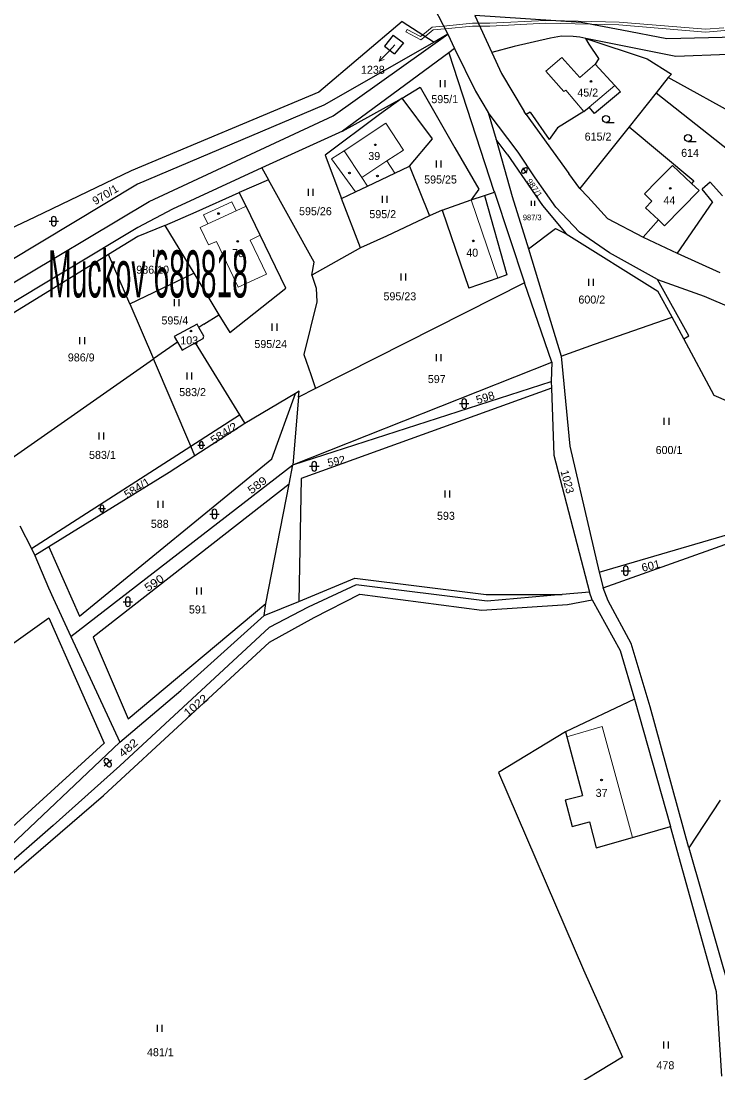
# Model space of a CAD drawing. Extents: x -744132 to -742433, y -984679 to -982287.
# Drawn here: x -743105 to -742956.9, y -983532.9 to -983309.4 of the extents above; entities that cross this region are included whole.
import ezdxf
from ezdxf.enums import TextEntityAlignment as Align

# ---------------------------------------------------------------- set-up
doc = ezdxf.new("R2010")
doc.units = 0
doc.header["$LTSCALE"] = 0.68
for name, color, linetype, lineweight in [('1', 7, 'Continuous', 25), ('13', 7, 'Continuous', 13), ('3', 7, 'Continuous', 25), ('4', 7, 'Continuous', 13), ('5', 7, 'Continuous', 25), ('7', 7, 'Continuous', 13)]:
    doc.layers.add(name, color=color, linetype=linetype, lineweight=lineweight)
doc.layers.add('2', color=7, linetype='Continuous')

msp = doc.modelspace()

# ---------------------------------------------------------------- linework, layer by layer
at = {"layer": '1'}
for p, q in [((-743035.42, -983270.81), (-743014.36, -983312.19)), ((-743024.03, -983309.45), (-743041.74, -983324.46)), ((-743024.03, -983309.45), (-743017.27, -983313.86)), ((-743008.63, -983308.2), (-743004.99, -983316.04)), ((-742986.03, -983309.69), (-743008.63, -983308.2)), ((-742977.36, -983311.34), (-742986.03, -983309.69)), ((-743038.73, -983329.48), (-743014.36, -983312.19)), ((-743014.36, -983312.19), (-743017.27, -983313.86)), ((-743014.36, -983312.19), (-743012.89, -983315.2)), ((-742967.82, -983313.13), (-742977.36, -983311.34)), ((-743017.27, -983313.86), (-743040.69, -983327.27)), ((-743025.95, -983312.38), (-743027.82, -983314.74)), ((-743025.95, -983312.38), (-743023.77, -983313.99)), ((-743023.77, -983313.99), (-743025.64, -983316.35)), ((-742992.51, -983313.01), (-743000.27, -983314.78)), ((-742990.17, -983312.59), (-742992.51, -983313.01)), ((-742987.7, -983312.64), (-742990.17, -983312.59)), ((-742986.3, -983312.77), (-742987.7, -983312.64)), ((-742985.04, -983313.07), (-742986.3, -983312.77)), ((-742985.04, -983313.07), (-742971.98, -983317.4)), ((-742965.92, -983316.88), (-742985.04, -983313.07)), ((-742984.3, -983314.25), (-742985.04, -983313.07)), ((-742982.27, -983317.36), (-742984.3, -983314.25)), ((-742953.06, -983312.8), (-742967.82, -983313.13)), ((-743014.11, -983316.1), (-743036.74, -983332.76)), ((-743027.82, -983314.74), (-743025.64, -983316.35)), ((-743012.89, -983315.2), (-743014.11, -983316.1)), ((-743014.11, -983316.1), (-743004.54, -983345.5)), ((-743012.89, -983315.2), (-743008.45, -983324.28)), ((-743000.27, -983314.78), (-743004.99, -983316.04)), ((-743004.99, -983316.04), (-743002.95, -983320.48)), ((-742954.79, -983316.51), (-742965.92, -983316.88)), ((-742982.27, -983317.36), (-742983.03, -983318.5)), ((-742983.03, -983318.5), (-742978.89, -983323.05)), ((-742971.98, -983317.4), (-742966.84, -983320.68)), ((-743002.95, -983320.48), (-742998.09, -983328.58)), ((-742966.84, -983320.68), (-742967.49, -983321.4)), ((-742978.89, -983323.05), (-742977.66, -983324.4)), ((-742967.49, -983321.4), (-742970.08, -983324.65)), ((-742948.13, -983332.12), (-742967.49, -983321.4)), ((-743041.74, -983324.46), (-743081.64, -983341.21)), ((-743008.45, -983324.28), (-743005.76, -983328.83)), ((-742977.66, -983324.4), (-742983.17, -983329.03)), ((-742970.08, -983324.65), (-742975.8, -983331.88)), ((-742970.08, -983324.65), (-742949.55, -983340.86)), ((-743040.69, -983327.27), (-743080.3, -983344.02)), ((-743036.74, -983332.76), (-743024.02, -983325.74)), ((-743024.02, -983325.74), (-743028.89, -983329.26)), ((-743017.59, -983334.39), (-743024.02, -983325.74)), ((-742985.42, -983328.59), (-742984.32, -983327.66)), ((-742983.17, -983329.03), (-742984.32, -983327.66)), ((-743077.8, -983347.74), (-743038.73, -983329.48)), ((-743028.89, -983329.26), (-743040.43, -983337.85)), ((-743005.76, -983328.83), (-743004.07, -983334.51)), ((-742999.37, -983337.21), (-743005.76, -983328.83)), ((-742997.67, -983329.25), (-742998.09, -983328.58)), ((-742996.84, -983328.74), (-742997.67, -983329.25)), ((-742997.67, -983329.25), (-742988.64, -983341.75)), ((-742996.84, -983328.74), (-742992.81, -983334.57)), ((-742985.42, -983328.59), (-742991.05, -983332.04)), ((-742991.05, -983332.04), (-742992.81, -983334.57)), ((-742975.8, -983331.88), (-742986.28, -983344.96)), ((-742975.8, -983331.88), (-742962.07, -983343.35)), ((-743036.74, -983332.76), (-743053.86, -983340.56)), ((-743022.48, -983340.2), (-743017.59, -983334.39)), ((-743004.07, -983334.51), (-743000.68, -983346.67)), ((-743001.7, -983337.68), (-743004.07, -983334.51)), ((-743040.43, -983337.85), (-743036.96, -983347.06)), ((-743001.7, -983337.68), (-742994.19, -983348.56)), ((-742995.8, -983342.65), (-742999.37, -983337.21)), ((-743081.64, -983341.21), (-743102.11, -983351.03)), ((-743053.86, -983340.56), (-743072.8, -983349.33)), ((-743053.86, -983340.56), (-743052.44, -983343.13)), ((-743025.58, -983341.67), (-743022.48, -983340.2)), ((-743022.48, -983340.2), (-743018.21, -983350.78)), ((-743052.44, -983343.13), (-743058.7, -983345.79)), ((-743031.41, -983344.43), (-743025.58, -983341.67)), ((-742991.41, -983348.94), (-742995.8, -983342.65)), ((-742986.28, -983344.96), (-742988.64, -983341.75)), ((-742962.07, -983343.35), (-742962.56, -983343.88)), ((-743080.3, -983344.02), (-743107.71, -983360.5)), ((-743036.96, -983347.06), (-743033.97, -983345.64)), ((-743033.97, -983345.64), (-743031.41, -983344.43)), ((-743006.52, -983346.43), (-743004.45, -983345.76)), ((-743004.54, -983345.5), (-743004.45, -983345.76)), ((-743004.45, -983345.76), (-742998.04, -983364.96)), ((-742986.28, -983344.96), (-742984.62, -983346.71)), ((-742960.95, -983345.39), (-742968.27, -983352.89)), ((-742960.95, -983345.39), (-742962.56, -983343.88)), ((-742958.59, -983343.6), (-742960.29, -983345.12)), ((-742958.08, -983347.8), (-742960.29, -983345.12)), ((-742958.59, -983343.6), (-742956, -983346.48)), ((-743123.79, -983375.17), (-743077.8, -983347.74)), ((-743067.84, -983349.87), (-743058.7, -983345.79)), ((-743057.18, -983348.71), (-743058.7, -983345.79)), ((-743032.88, -983357.57), (-743036.96, -983347.06)), ((-743015.56, -983349.54), (-743009.41, -983347.37)), ((-743009.41, -983347.37), (-743006.52, -983346.43)), ((-743006.52, -983346.43), (-743001.77, -983363.3)), ((-743000.68, -983346.67), (-742997.17, -983357.74)), ((-742984.62, -983346.71), (-742980.38, -983351.31)), ((-742958.08, -983347.8), (-742965.59, -983358.65)), ((-743072.8, -983349.33), (-743080.22, -983353.24)), ((-743074.49, -983352.84), (-743067.84, -983349.87)), ((-743054.21, -983354.89), (-743057.18, -983348.71)), ((-743015.56, -983349.54), (-743018.21, -983350.78)), ((-743015.56, -983349.54), (-743009.85, -983366.15)), ((-742994.19, -983348.56), (-742989.17, -983354.57)), ((-742986.38, -983354.23), (-742991.41, -983348.94)), ((-743102.11, -983351.03), (-743115.65, -983357.39)), ((-743018.21, -983350.78), (-743027.39, -983355.06)), ((-742980.38, -983351.31), (-742972.82, -983355.31)), ((-742969.6, -983351.58), (-742972.82, -983355.31)), ((-742969.6, -983351.58), (-742968.27, -983352.89)), ((-743080.22, -983353.24), (-743116.02, -983374.77)), ((-743074.49, -983352.84), (-743080.18, -983355.17)), ((-743074.49, -983352.84), (-743068.27, -983362.96)), ((-742997.17, -983357.74), (-742991.46, -983353.48)), ((-742991.46, -983353.48), (-742989.17, -983354.57)), ((-742989.17, -983354.57), (-742969.73, -983366.75)), ((-742980.01, -983358.58), (-742986.38, -983354.23)), ((-743080.18, -983355.17), (-743086.44, -983359)), ((-743048.79, -983366.15), (-743054.21, -983354.89)), ((-743027.39, -983355.06), (-743032.88, -983357.57)), ((-742972.82, -983355.31), (-742965.59, -983358.65)), ((-743086.44, -983359), (-743114.52, -983376.21)), ((-743081.89, -983369.48), (-743086.44, -983359)), ((-743032.88, -983357.57), (-743043.21, -983363.39)), ((-742997.17, -983357.74), (-742995.05, -983364.75)), ((-742969.76, -983364.29), (-742980.01, -983358.58)), ((-742965.59, -983358.65), (-742956.57, -983362.81)), ((-743081.89, -983369.48), (-743068.27, -983362.96)), ((-743068.27, -983362.96), (-743063, -983371.81)), ((-743043.21, -983363.39), (-743042.33, -983366.15)), ((-743001.77, -983363.3), (-743003.7, -983363.98)), ((-742998.04, -983364.96), (-743042.45, -983387.46)), ((-743003.7, -983363.98), (-743009.85, -983366.15)), ((-742992.26, -983381.84), (-742998.04, -983364.96)), ((-742995.05, -983364.75), (-742990.26, -983380.54)), ((-742969.76, -983364.29), (-742959.86, -983367.82)), ((-742963.15, -983376.22), (-742969.76, -983364.29)), ((-743060.68, -983375.56), (-743048.79, -983366.15)), ((-743042.33, -983366.15), (-743042.17, -983369.01)), ((-742959.86, -983367.82), (-742954.09, -983370.28)), ((-743081.89, -983369.48), (-743076.85, -983381.14)), ((-743042.17, -983369.01), (-743044.9, -983380.24)), ((-743066.2, -983373.74), (-743063, -983371.81)), ((-743063, -983371.81), (-743060.68, -983375.56)), ((-742983.17, -983378.05), (-742966.71, -983372.27)), ((-743067.59, -983373.78), (-743072.47, -983376.37)), ((-743067.23, -983374.45), (-743067.59, -983373.78)), ((-743066.2, -983373.74), (-743067.23, -983374.45)), ((-743066.2, -983376.35), (-743067.23, -983374.45)), ((-743072.47, -983376.37), (-743071.77, -983377.59)), ((-743068.04, -983377.76), (-743066.29, -983376.81)), ((-743066.29, -983376.81), (-743066.2, -983376.35)), ((-742964.19, -983376.89), (-742963.15, -983376.22)), ((-742957.77, -983388.91), (-742964.19, -983376.89)), ((-743071.77, -983377.59), (-743076.85, -983381.14)), ((-743071.77, -983377.59), (-743070.81, -983379.26)), ((-743070.81, -983379.26), (-743068.04, -983377.76)), ((-742990.26, -983380.54), (-742983.17, -983378.05)), ((-743108.52, -983403.29), (-743076.85, -983381.14)), ((-743068.94, -983399.66), (-743076.85, -983381.14)), ((-743044.9, -983380.24), (-743043.47, -983384.43)), ((-742990.26, -983380.54), (-742988.4, -983399.7)), ((-743047.27, -983403.67), (-742992.26, -983381.84)), ((-742992.26, -983381.84), (-742992.36, -983385.92)), ((-743047.27, -983403.67), (-742992.36, -983385.92)), ((-743043.47, -983384.43), (-743042.45, -983387.46)), ((-742992.36, -983385.92), (-742992.33, -983387.4)), ((-743045.89, -983388.03), (-743046.72, -983388.52)), ((-743042.45, -983387.46), (-743046.08, -983389.3)), ((-743046.08, -983389.3), (-743045.89, -983388.03)), ((-742992.33, -983387.4), (-743045.48, -983406.58)), ((-742992.33, -983387.4), (-742991.79, -983401.6)), ((-743046.72, -983388.52), (-743057.49, -983394.87)), ((-743051.73, -983402.37), (-743046.72, -983388.52)), ((-743046.08, -983389.3), (-743047.27, -983403.67)), ((-742954.64, -983390.28), (-742957.77, -983388.91)), ((-743068.94, -983399.66), (-743058.63, -983393.03)), ((-743057.49, -983394.87), (-743068.06, -983401.72)), ((-743102.82, -983421.45), (-743068.94, -983399.66)), ((-743068.06, -983401.72), (-743068.94, -983399.66)), ((-742991.79, -983401.6), (-742984.24, -983430.7)), ((-742988.4, -983399.7), (-742982.15, -983426.48)), ((-743094.45, -983440.1), (-743047.27, -983403.67)), ((-743092.61, -983435.78), (-743051.73, -983402.37)), ((-743068.06, -983401.72), (-743073.57, -983405.29)), ((-743048.05, -983407.76), (-743047.27, -983403.67)), ((-743073.57, -983405.29), (-743099.13, -983421.05)), ((-743048.05, -983407.76), (-743089.67, -983440.29)), ((-743052.97, -983433.12), (-743048.05, -983407.76)), ((-743105.28, -983416.64), (-743102.82, -983421.45)), ((-742982.15, -983426.48), (-742954.34, -983418.3)), ((-743102.82, -983421.45), (-743102.08, -983422.89)), ((-743099.13, -983421.05), (-743102.08, -983422.89)), ((-743099.13, -983421.05), (-743092.61, -983435.78)), ((-742981.35, -983429.8), (-742953.31, -983419.82)), ((-743102.08, -983422.89), (-743099.18, -983429.82)), ((-742982.15, -983426.48), (-742981.35, -983429.8)), ((-743099.18, -983429.82), (-743098.21, -983432.01)), ((-743033.82, -983429.18), (-743044.04, -983433.86)), ((-743005.99, -983432.63), (-743033.82, -983429.18)), ((-742980.29, -983432.52), (-742981.35, -983429.8)), ((-743098.21, -983432.01), (-743094.45, -983440.1)), ((-743053.39, -983435.69), (-743046, -983432.72)), ((-743042.77, -983436.07), (-743033.06, -983431.15)), ((-743033.06, -983431.15), (-743007.08, -983434.54)), ((-742990.05, -983431.22), (-743005.99, -983432.63)), ((-742984.24, -983430.7), (-742990.05, -983431.22)), ((-742988.94, -983433.31), (-742983.67, -983432.36)), ((-742983.67, -983432.36), (-742984.24, -983430.7)), ((-742983.67, -983432.36), (-742977.71, -983443.12)), ((-742975.41, -983441.62), (-742980.29, -983432.52)), ((-743082.25, -983457.59), (-743052.97, -983433.12)), ((-743053.39, -983435.69), (-743052.97, -983433.12)), ((-743044.04, -983433.86), (-743052.32, -983438.22)), ((-743007.08, -983434.54), (-742988.94, -983433.31)), ((-743123.13, -983453.28), (-743099.09, -983436.19)), ((-743099.09, -983436.19), (-743087.36, -983462.79)), ((-743071.04, -983451.59), (-743053.39, -983435.69)), ((-743052.23, -983441.33), (-743042.77, -983436.07)), ((-743052.32, -983438.22), (-743084.04, -983467.59)), ((-743094.45, -983440.1), (-743084, -983462.6)), ((-743089.67, -983440.29), (-743082.25, -983457.59)), ((-743087.48, -983473.88), (-743052.23, -983441.33)), ((-742971.35, -983455.07), (-742975.41, -983441.62)), ((-742977.71, -983443.12), (-742974.65, -983453.47)), ((-743084, -983462.6), (-743071.04, -983451.59)), ((-742974.65, -983453.47), (-742989.34, -983460.35)), ((-742974.65, -983453.47), (-742967.03, -983480.49)), ((-742963.11, -983485), (-742971.35, -983455.07)), ((-742989.34, -983460.35), (-743003.6, -983468.99)), ((-742989.34, -983460.35), (-742989.05, -983461.43)), ((-742989.05, -983461.43), (-742985.76, -983473.89)), ((-743087.36, -983462.79), (-743127.53, -983499.42)), ((-743084, -983462.6), (-743125.36, -983501.7)), ((-743084.04, -983467.59), (-743098.21, -983480.3)), ((-743003.6, -983468.99), (-742985.48, -983510.94)), ((-743122.91, -983504.38), (-743087.48, -983473.88)), ((-742989.39, -983474.84), (-742985.76, -983473.89)), ((-742989.39, -983474.84), (-742987.9, -983480.48)), ((-742956.48, -983474.86), (-742963.11, -983485)), ((-742987.9, -983480.48), (-742984.27, -983479.51)), ((-742984.27, -983479.51), (-742982.82, -983485)), ((-743098.21, -983480.3), (-743124.44, -983503.22)), ((-742975.13, -983482.8), (-742967.03, -983480.49)), ((-742957.26, -983515.6), (-742967.03, -983480.49)), ((-742982.82, -983485), (-742975.13, -983482.8)), ((-742963.11, -983485), (-742954.27, -983515.9)), ((-742985.48, -983510.94), (-742977.21, -983529.47)), ((-742956.14, -983533.56), (-742957.26, -983515.6)), ((-742977.21, -983529.47), (-742989.65, -983537))]:
    msp.add_line(p, q, dxfattribs=at)
for points in [[(-743024.02, -983325.74), (-743020.24, -983323.42), (-743012.82, -983336.31), (-743007.77, -983345.06), (-743009.41, -983347.37)], [(-743043.21, -983363.39), (-743042.74, -983360.61), (-743052.44, -983343.13)], [(-742964.19, -983376.89), (-742966.71, -983372.27), (-742969.73, -983366.75)], [(-743068.04, -983377.76), (-743058.63, -983393.03), (-743057.49, -983394.87)], [(-743045.48, -983406.58), (-743046, -983432.72), (-743034.13, -983427.73)], [(-743034.13, -983427.73), (-743006.21, -983431.17), (-742990.05, -983431.22)]]:
    msp.add_lwpolyline(points, dxfattribs=at)
at = {"layer": '13'}
for points in [[(-743015.25, -983310.43), (-743014.96, -983311.01), (-743009.11, -983310.43), (-743007.59, -983310.44), (-743007.87, -983309.84), (-743009.13, -983309.83)], [(-743015.25, -983310.43), (-743017.67, -983310.67), (-743019.67, -983312.29), (-743020.14, -983312.67), (-743022.95, -983311.15), (-743023.23, -983311.67), (-743020.08, -983313.39), (-743019.15, -983312.64), (-743017.43, -983311.25), (-743014.96, -983311.01)]]:
    msp.add_lwpolyline(points, close=True, dxfattribs=at)
msp.add_lwpolyline([(-742955.72, -983310.79), (-742959.6, -983311.1), (-742977.96, -983309.6), (-742992.46, -983309.27), (-742993.59, -983309.24), (-743005.41, -983309.85), (-743007.87, -983309.84), (-743007.59, -983310.44), (-743005.39, -983310.45), (-742993.59, -983309.84), (-742984.09, -983310.06), (-742978, -983310.2), (-742959.6, -983311.7), (-742955.5, -983311.37)], dxfattribs=at)
at = {"layer": '3'}
for p, q in [((-743015.871, -983323.43), (-743015.871, -983321.93)), ((-743014.87, -983323.43), (-743014.87, -983321.93)), ((-742980.743, -983330.93), (-742978.993, -983330.93)), ((-742963.313, -983334.97), (-742961.563, -983334.97)), ((-743016.761, -983340.51), (-743016.761, -983339.01)), ((-743015.76, -983340.51), (-743015.76, -983339.01)), ((-742998.003, -983340.618), (-742998.562, -983341.04)), ((-742998.493, -983340.55), (-742997.65, -983341.669)), ((-742998.141, -983341.6), (-742997.581, -983341.178)), ((-743043.921, -983346.53), (-743043.921, -983345.03)), ((-743042.92, -983346.53), (-743042.92, -983345.03)), ((-743028.231, -983347.99), (-743028.231, -983346.49)), ((-743027.23, -983347.99), (-743027.23, -983346.49)), ((-742996.568, -983348.62), (-742996.568, -983347.57)), ((-742995.867, -983348.62), (-742995.867, -983347.57)), ((-743099.071, -983351.901), (-743097.069, -983351.901)), ((-743098.571, -983351.401), (-743098.571, -983352.402)), ((-743097.569, -983352.402), (-743097.569, -983351.401)), ((-743076.791, -983359.48), (-743076.791, -983357.98)), ((-743075.79, -983359.48), (-743075.79, -983357.98)), ((-743024.271, -983364.52), (-743024.271, -983363.02)), ((-743023.27, -983364.52), (-743023.27, -983363.02)), ((-742984.361, -983365.61), (-742984.361, -983364.11)), ((-742983.36, -983365.61), (-742983.36, -983364.11)), ((-743072.391, -983369.97), (-743072.391, -983368.47)), ((-743071.39, -983369.97), (-743071.39, -983368.47)), ((-743051.631, -983375.16), (-743051.631, -983373.66)), ((-743050.63, -983375.16), (-743050.63, -983373.66)), ((-743092.491, -983378.05), (-743092.491, -983376.55)), ((-743091.49, -983378.05), (-743091.49, -983376.55)), ((-743016.771, -983381.66), (-743016.771, -983380.16)), ((-743015.77, -983381.66), (-743015.77, -983380.16)), ((-743069.741, -983385.53), (-743069.741, -983384.03)), ((-743068.74, -983385.53), (-743068.74, -983384.03)), ((-743011.361, -983390.151), (-743011.361, -983391.152)), ((-743010.359, -983391.152), (-743010.359, -983390.151)), ((-743011.861, -983390.651), (-743009.859, -983390.651)), ((-742968.341, -983395.18), (-742968.341, -983393.68)), ((-742967.34, -983395.18), (-742967.34, -983393.68)), ((-743088.421, -983398.3), (-743088.421, -983396.8)), ((-743087.42, -983398.3), (-743087.42, -983396.8)), ((-743067.075, -983399.075), (-743067.075, -983399.826)), ((-743066.325, -983399.826), (-743066.325, -983399.075)), ((-743067.451, -983399.451), (-743065.949, -983399.451)), ((-743043.211, -983403.471), (-743043.211, -983404.472)), ((-743042.209, -983404.472), (-743042.209, -983403.471)), ((-743043.711, -983403.971), (-743041.709, -983403.971)), ((-743014.931, -983410.6), (-743014.931, -983409.1)), ((-743013.93, -983410.6), (-743013.93, -983409.1)), ((-743088.185, -983412.575), (-743088.185, -983413.326)), ((-743087.435, -983413.326), (-743087.435, -983412.575)), ((-743075.851, -983412.77), (-743075.851, -983411.27)), ((-743074.85, -983412.77), (-743074.85, -983411.27)), ((-743088.561, -983412.951), (-743087.059, -983412.951)), ((-743064.921, -983414.101), (-743062.919, -983414.101)), ((-743064.421, -983413.601), (-743064.421, -983414.602)), ((-743063.419, -983414.602), (-743063.419, -983413.601)), ((-742977.541, -983426.151), (-742975.539, -983426.151)), ((-742977.041, -983425.651), (-742977.041, -983426.652)), ((-742976.039, -983426.652), (-742976.039, -983425.651)), ((-743067.651, -983431.19), (-743067.651, -983429.69)), ((-743066.65, -983431.19), (-743066.65, -983429.69)), ((-743083.321, -983432.741), (-743081.319, -983432.741)), ((-743082.821, -983432.241), (-743082.821, -983433.242)), ((-743081.819, -983433.242), (-743081.819, -983432.241)), ((-743087.367, -983467.574), (-743085.811, -983466.314)), ((-743085.885, -983467.018), (-743086.515, -983466.24)), ((-743087.293, -983466.87), (-743086.663, -983467.648)), ((-743076.011, -983524.14), (-743076.011, -983522.64)), ((-743075.01, -983524.14), (-743075.01, -983522.64)), ((-742968.421, -983527.67), (-742968.421, -983526.17)), ((-742967.42, -983527.67), (-742967.42, -983526.17))]:
    msp.add_line(p, q, dxfattribs=at)
for centre in [(-742980.7429, -983330.1798), (-742963.3129, -983334.2198)]:
    msp.add_circle(centre, 0.75, dxfattribs=at)
for centre, radius, start, end in [((-742998.351, -983341.3197), 0.35, 127, 306.98789), ((-742997.7919, -983340.8985), 0.35, 307, 127), ((-743098.07, -983351.4009), 0.5, 0, 180), ((-743098.07, -983352.4009), 0.5, 180, 359.98789), ((-743010.86, -983390.1509), 0.5, 0, 180), ((-743010.86, -983391.1509), 0.5, 180, 359.98789), ((-743066.7, -983399.0757), 0.375, 0, 180), ((-743066.7, -983399.8257), 0.375, 180, 359.98789), ((-743042.71, -983403.4709), 0.5, 0, 180), ((-743042.71, -983404.4709), 0.5, 180, 359.98789), ((-743087.81, -983412.5757), 0.375, 0, 180), ((-743087.81, -983413.3257), 0.375, 180, 359.98789), ((-743063.92, -983413.6009), 0.5, 0, 180), ((-743063.92, -983414.6009), 0.5, 180, 359.98789), ((-742976.54, -983425.6509), 0.5, 0, 180), ((-742976.54, -983426.6509), 0.5, 180, 359.98789), ((-743082.32, -983432.2409), 0.5, 0, 180), ((-743082.32, -983433.2409), 0.5, 180, 359.98789), ((-743086.9034, -983466.555), 0.5, 39, 219), ((-743086.2741, -983467.3321), 0.5, 219, 38.98789)]:
    msp.add_arc(centre, radius, start, end, dxfattribs=at)
at = {"layer": '4'}
for p, q in [((-742993.51, -983320.01), (-742990.09, -983317.13)), ((-742990.09, -983317.13), (-742986.31, -983321.35)), ((-742983.03, -983318.5), (-742986.31, -983321.35)), ((-742989.69, -983324.34), (-742993.51, -983320.01)), ((-742984.32, -983327.66), (-742978.89, -983323.05)), ((-742989.69, -983324.34), (-742989.28, -983324.09)), ((-742989.28, -983324.09), (-742985.42, -983328.59)), ((-743036.39, -983336.92), (-743027.53, -983331.05)), ((-743027.53, -983331.05), (-743023.78, -983336.77)), ((-743027.27, -983339.08), (-743023.78, -983336.77)), ((-743039.03, -983338.67), (-743036.39, -983336.92)), ((-743033.97, -983345.64), (-743039.03, -983338.67)), ((-743036.39, -983336.92), (-743032.64, -983342.64)), ((-743032.64, -983342.64), (-743027.27, -983339.08)), ((-743027.27, -983339.08), (-743025.58, -983341.67)), ((-742966.62, -983340.07), (-742969.84, -983343.34)), ((-742962.56, -983343.88), (-742966.62, -983340.07)), ((-743032.64, -983342.64), (-743031.41, -983344.43)), ((-742969.84, -983343.34), (-742972.56, -983346.1)), ((-743003.7, -983363.98), (-743009.41, -983347.37)), ((-742970.97, -983347.66), (-742972.56, -983346.1)), ((-742970.97, -983347.66), (-742972.32, -983349.03)), ((-743059.33, -983349.7), (-743065.31, -983352.45)), ((-743057.18, -983348.71), (-743059.33, -983349.7)), ((-742972.32, -983349.03), (-742969.6, -983351.58)), ((-743056.33, -983355.93), (-743054.21, -983354.89)), ((-743052.87, -983363.14), (-743056.33, -983355.93)), ((-743058.85, -983365.89), (-743052.87, -983363.14)), ((-743058.85, -983365.89), (-743059.92, -983363.67)), ((-742989.05, -983461.43), (-742981.57, -983459.24)), ((-742981.57, -983459.24), (-742975.13, -983482.8))]:
    msp.add_line(p, q, dxfattribs=at)
for points in [[(-743065.31, -983352.45), (-743066.22, -983350.55), (-743060.24, -983347.8), (-743059.33, -983349.7)], [(-743065.31, -983352.45), (-743066.96, -983353.21), (-743065.16, -983356.95), (-743063.51, -983356.19), (-743059.92, -983363.67)]]:
    msp.add_lwpolyline(points, dxfattribs=at)
at = {"layer": '5'}
for centre in [(-742983.9368, -983322.2092), (-743029.7568, -983335.6692), (-743035.2368, -983341.6492), (-743029.2968, -983342.2792), (-742967.0768, -983344.9192), (-743063.0468, -983350.2692), (-743058.9768, -983356.1892), (-743008.9268, -983356.0692), (-743068.9068, -983375.2292), (-742981.6868, -983470.6092)]:
    msp.add_circle(centre, 0.175, dxfattribs=at)
at = {"layer": '7'}
msp.add_line((-743028.915, -983317.909), (-743027.859, -983317.536), dxfattribs=at)
msp.add_lwpolyline([(-743025.58, -983314.45), (-743026.83, -983315.75), (-743028.915, -983317.909), (-743028.579, -983316.84)], dxfattribs=at)

# ---------------------------------------------------------------- texts
at = {"layer": '2'}
for s, p in [('1238', (-743030.26, -983320.575)), ('595/25', (-743015.89, -983343.885)), ('595/26', (-743042.47, -983350.625)), ('986/10', (-743077.05, -983363.045)), ('600/2', (-742983.75, -983369.395)), ('103', (-743069.279, -983378.065)), ('595/24', (-743051.96, -983378.835)), ('583/2', (-743068.57, -983389.055)), ('583/1', (-743087.72, -983402.395)), ('600/1', (-742967.34, -983401.355))]:
    msp.add_text(s, height=1.7, dxfattribs=at).set_placement(p, align=Align.CENTER)
for s, height, p in [('595/1', 1.7, (-743017.84, -983326.815)), ('45/2', 1.7, (-742986.82, -983325.415)), ('615/2', 1.7, (-742985.27, -983334.775)), ('614', 1.7, (-742964.76, -983338.225)), ('39', 1.7, (-743031.24, -983338.895)), ('44', 1.7, (-742968.52, -983348.295)), ('595/2', 1.7, (-743031.01, -983351.245)), ('987/3', 1.19, (-742998.4, -983351.687)), ('70', 1.7, (-743060.18, -983359.525)), ('40', 1.7, (-743010.42, -983359.435)), ('595/23', 1.7, (-743028.01, -983368.705)), ('595/4', 1.7, (-743075.18, -983373.825)), ('986/9', 1.7, (-743095.07, -983381.685)), ('597', 1.7, (-743018.59, -983386.285)), ('593', 1.7, (-743016.64, -983415.335)), ('588', 1.7, (-743077.44, -983417.035)), ('591', 1.7, (-743069.35, -983435.235)), ('37', 1.7, (-742982.93, -983474.195)), ('481/1', 1.7, (-743078.26, -983529.285)), ('478', 1.7, (-742970.01, -983532.055))]:
    msp.add_text(s, height=height, dxfattribs=at).set_placement(p)
for s, height, rotation, width, p in [('987/1', 1.19, 305, 1.1, (-742997.663, -983343.37)), ('970/1', 1.7, 31, 1.05, (-743089.241, -983348.514)), ('598', 1.7, 17, 1.05, (-743008.045, -983390.746)), ('589', 1.7, 37, 1.15, (-743056.074, -983409.949)), ('601', 1.7, 14, 1.05, (-742972.947, -983426.392)), ('590', 1.7, 34, 1.15, (-743078.072, -983430.672)), ('1022', 1.7, 40, 1.15, (-743069.576, -983457.275)), ('482', 1.7, 41, 1.2, (-743083.401, -983465.91))]:
    msp.add_text(s, height=height, rotation=rotation, dxfattribs=dict(at, width=width)).set_placement(p)
for s, rotation, width, p in [('584/2', 33, 1.1, (-743061.4529, -983397.6334)), ('584/1', 32, 1.05, (-743079.9149, -983409.2971))]:
    msp.add_text(s, height=1.7, rotation=rotation, dxfattribs=dict(at, width=width)).set_placement(p, align=Align.CENTER)
for s, rotation, p in [('592', 12, (-743039.711, -983404.095)), ('1023', 285, (-742990.41, -983405.019))]:
    msp.add_text(s, height=1.7, rotation=rotation, dxfattribs=at).set_placement(p)
at = {"layer": '7', "width": 0.45}
msp.add_text('Muckov 680818', height=10, dxfattribs=at).set_placement((-743078.049, -983368.093), align=Align.CENTER)

doc.saveas('drawing.dxf')
